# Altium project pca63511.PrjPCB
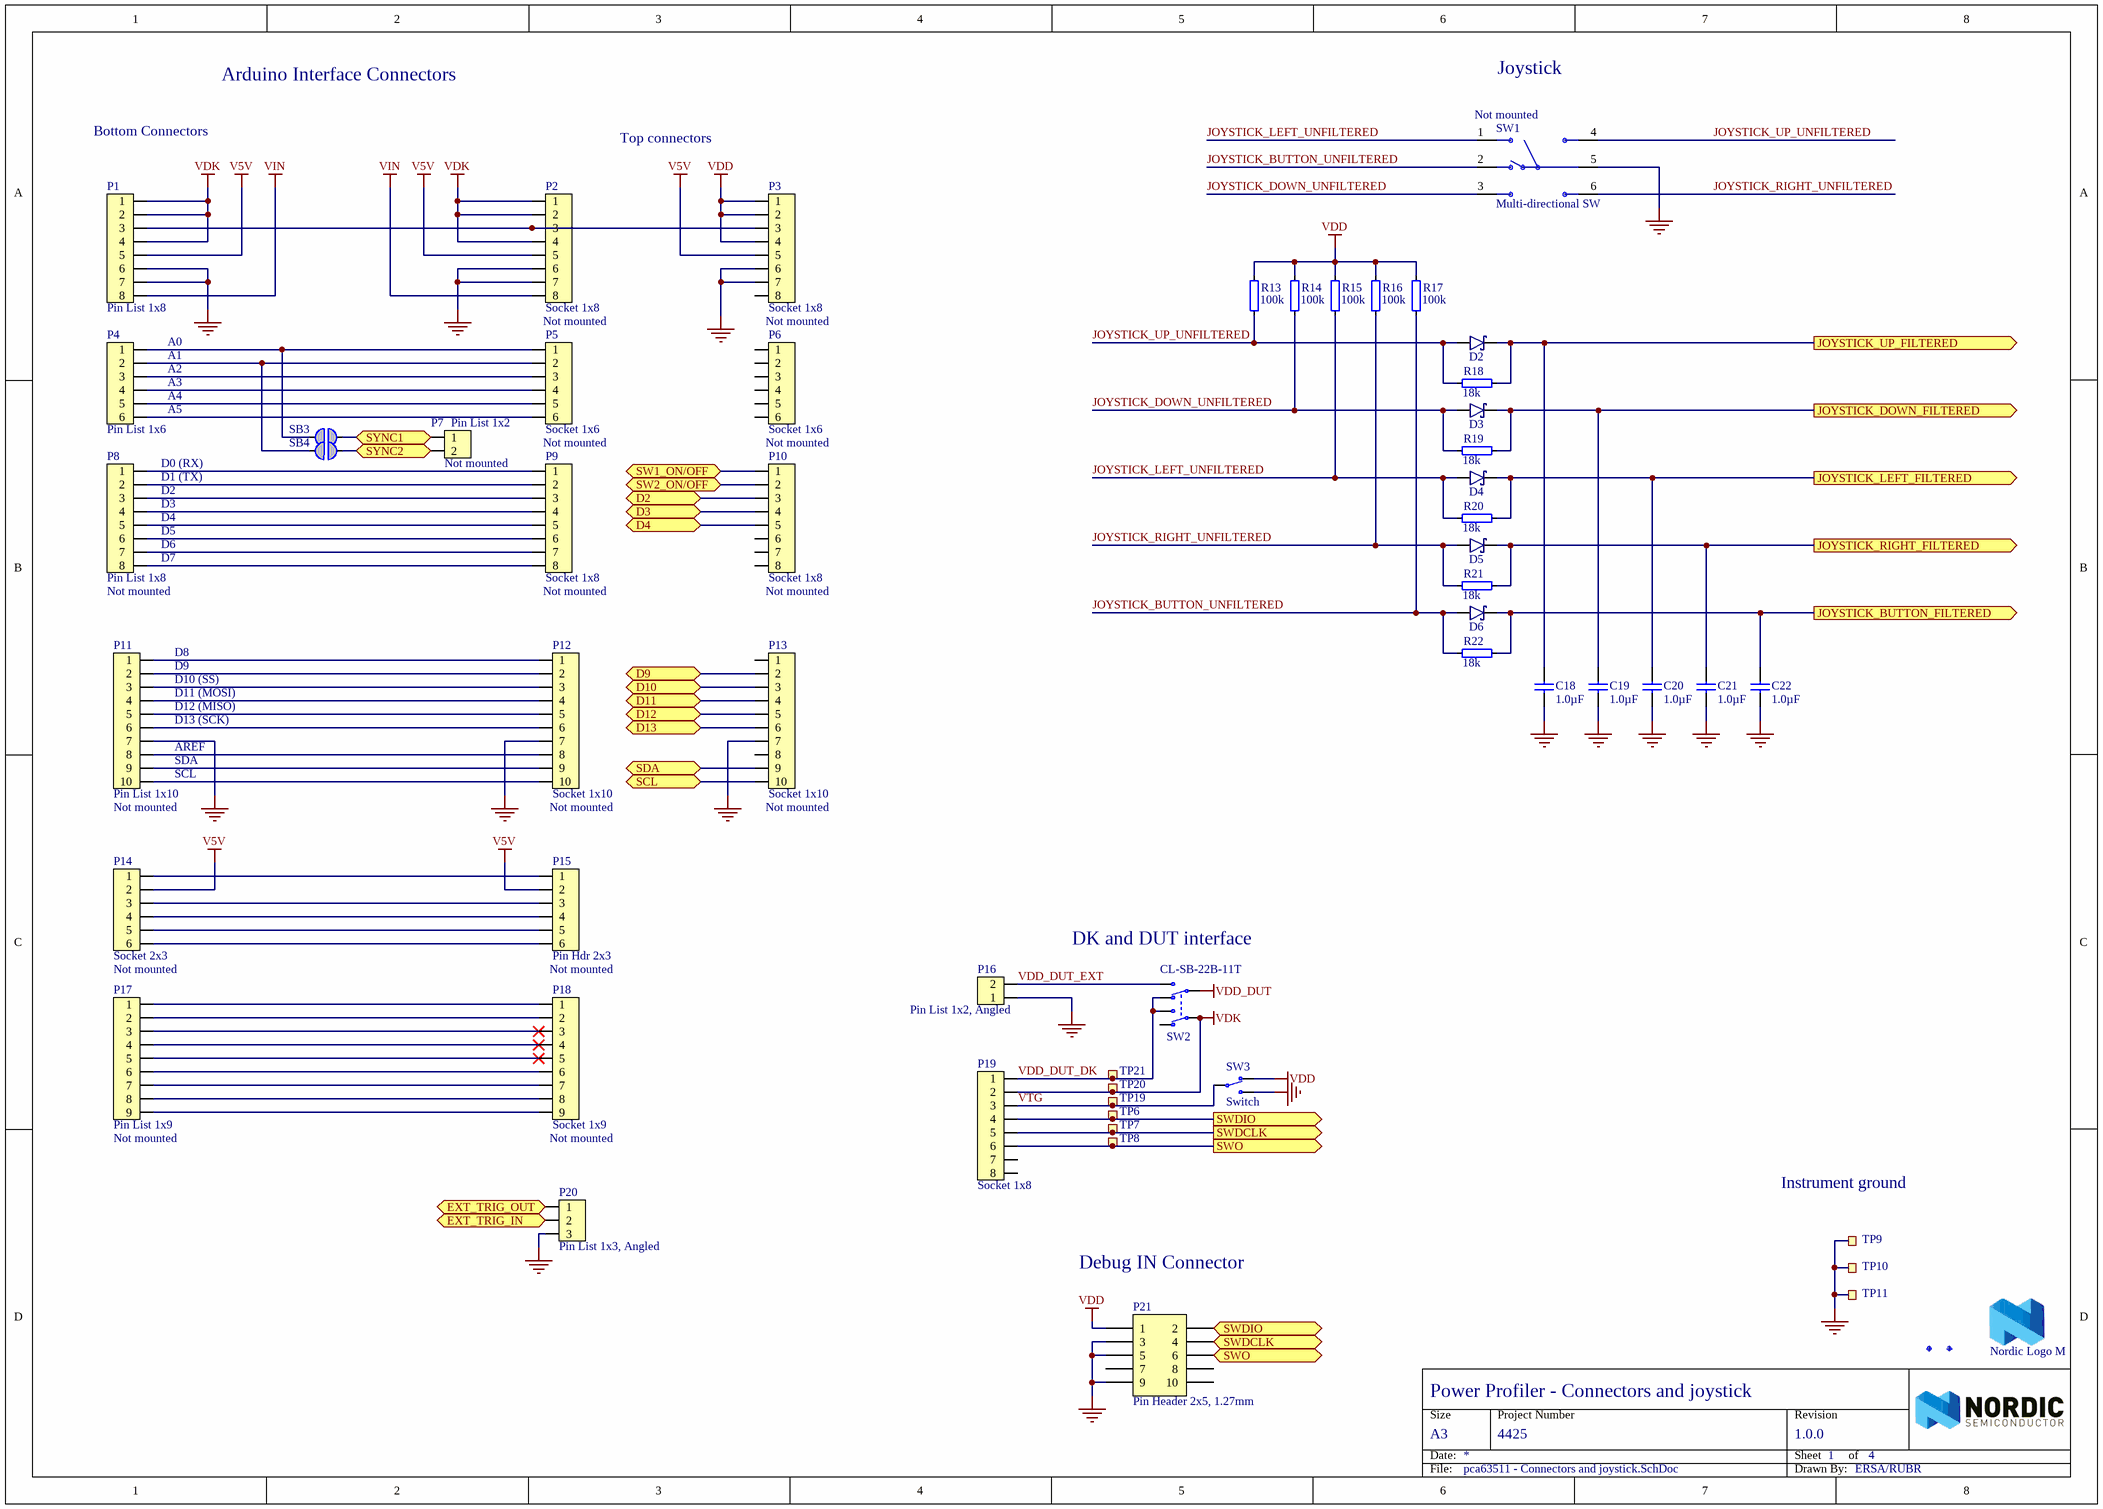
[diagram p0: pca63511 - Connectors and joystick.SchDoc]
4 sheets, 220 parts. Net scope: flat (ports and power ports of the same name join across sheets).
Board file: 400102.PcbDoc
Sheets:
  pca63511 - Connectors and joystick.SchDoc
  pca63511 - Current Measurement.SchDoc
  pca63511 - Automatic switch.SchDoc
  pca63511 - Power supply.SchDoc

## Sheet pca63511 - Connectors and joystick.SchDoc: Power Profiler - Connectors and joystick
size A3; Revision: 1.0.0; SheetNumber: 1; SheetTotal: 4; DrawnBy: ERSA/RUBR; ProjectNumber: 4425; DocumentSize: A3; PCBRevision: 0232RUBR; PCAName: PCA63511; PCBNumber: 400102

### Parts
C18  1.0µF  [CAPC1005X04L]
C19  1.0µF  [CAPC1005X04L]
C20  1.0µF  [CAPC1005X04L]
C21  1.0µF  [CAPC1005X04L]
C22  1.0µF  [CAPC1005X04L]
D2  1PS79SB30.115  [SOD-523]  (value not drawn)
D3  1PS79SB30.115  [SOD-523]  (value not drawn)
D4  1PS79SB30.115  [SOD-523]  (value not drawn)
D5  1PS79SB30.115  [SOD-523]  (value not drawn)
D6  1PS79SB30.115  [SOD-523]  (value not drawn)
Fid1  Fiducial mark  [Fiducial]  (value not drawn)
Fid2  Fiducial mark  [Fiducial]  (value not drawn)
LOGO1  Nordic Logo M  [NORDIC_LOGO_M]  (no BOM)
P1  Pin List 1x8  [LIST_1x8_SMD]
P2  Socket 1x8  Assembly: Not mounted  [SOCKET_1x8_SMD]
P3  Socket 1x8  Assembly: Not mounted  [SOCKET_1x8_SMD]
P4  Pin List 1x6  [LIST_1x6_SMD]
P5  Socket 1x6  Assembly: Not mounted  [SOCKET_1x6_SMD]
P6  Socket 1x6  Assembly: Not mounted  [SOCKET_1x6_SMD]
P7  Pin List 1x2  Assembly: Not mounted  [LIST_1x2]
P8  Pin List 1x8  Assembly: Not mounted  [LIST_1x8_SMD]
P9  Socket 1x8  Assembly: Not mounted  [SOCKET_1x8_SMD]
P10  Socket 1x8  Assembly: Not mounted  [SOCKET_1x8_SMD]
P11  Pin List 1x10  Assembly: Not mounted  [LIST_1x10_SMD]
P12  Socket 1x10  Assembly: Not mounted  [SOCKET_1x10_SMD]
P13  Socket 1x10  Assembly: Not mounted  [SOCKET_1x10_SMD]
P14  Socket 2x3  Assembly: Not mounted  [SOCKET_2x3_SMD-2.54mm-bottom]
P15  Pin Hdr 2x3  Assembly: Not mounted  [Molex 15-91-2060]
P16  Pin List 1x2, Angled  [LIST_ANG_1x2-SMD-2.54MM]
P17  Pin List 1x9  Assembly: Not mounted  [LIST_1x9_SMD]
P18  Socket 1x9  Assembly: Not mounted  [SOCKET_1x9_SMD]
P19  Socket 1x8  [SOCKET_1x8_SMD]
P20  Pin List 1x3, Angled  [LIST_ANG_1x3-SMD-2.54MM]
P21  Pin Header 2x5, 1.27mm  [HDR_2x5-SMD-1.27mm-K]
R13  100k  [RESC1005X04L]
R14  100k  [RESC1005X04L]
R15  100k  [RESC1005X04L]
R16  100k  [RESC1005X04L]
R17  100k  [RESC1005X04L]
R18  18k  [RESC1005X04L]
R19  18k  [RESC1005X04L]
R20  18k  [RESC1005X04L]
R21  18k  [RESC1005X04L]
R22  18k  [RESC1005X04L]
SB3  Solderbridge  [Solderbridge]  (value not drawn)  (no BOM)
SB4  Solderbridge  [Solderbridge]  (value not drawn)  (no BOM)
SW1  Multi-directional SW  Assembly: Not mounted  [ALPS_SKRHAAE010]
SW2  CL-SB-22B-11T  [CL-SB-22B-1x]
SW3  Switch  [CJS-120xA]
TP6  Ø1.5mm,SMD  [TP_SMD_Ø1.5mm]  (value not drawn)  (no BOM)
TP7  Ø1.5mm,SMD  [TP_SMD_Ø1.5mm]  (value not drawn)  (no BOM)
TP8  Ø1.5mm,SMD  [TP_SMD_Ø1.5mm]  (value not drawn)  (no BOM)
TP9  TP  [TEST_POINT_5001]  (value not drawn)  (no BOM)
TP10  TP  [TEST_POINT_5001]  (value not drawn)  (no BOM)
TP11  Ø1.0mm,SMD  [TP_SMD_Ø1.5MM]  (value not drawn)  (no BOM)
TP19  Ø1.5mm,SMD  [TP_SMD_Ø1.5mm]  (value not drawn)  (no BOM)
TP20  Ø1.5mm,SMD  [TP_SMD_Ø1.5mm]  (value not drawn)  (no BOM)
TP21  Ø1.5mm,SMD  [TP_SMD_Ø1.5mm]  (value not drawn)  (no BOM)

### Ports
D2 (bidir), D3 (bidir), D4 (bidir), D9 (bidir), D10 (bidir), D11 (bidir), D12 (bidir), D13 (bidir), EXT_TRIG_IN (out), EXT_TRIG_OUT (in), JOYSTICK_BUTTON_FILTERED (out), JOYSTICK_DOWN_FILTERED (out), JOYSTICK_LEFT_FILTERED (out), JOYSTICK_RIGHT_FILTERED (out), JOYSTICK_UP_FILTERED (out), SCL (bidir), SDA (bidir), SW1_ON/OFF (bidir), SW2_ON/OFF (bidir), SWDCLK (out), SWDIO (out), SWO (out), SYNC1 (bidir), SYNC2 (bidir)

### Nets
GND: C18.2 C19.2 C20.2 C21.2 C22.2 P1.6 P1.7 P2.6 P2.7 P3.6 P3.7 P11.7 P12.7 P13.7 P16.1 P20.3 P21.3 P21.5 P21.9 SW1.5 SW3.3(N.O) TP9.1 TP10.1 TP11.1
V5V: P1.5 P2.5 P3.5 P14.2 P15.2
VDD: P3.1 P3.2 P3.4 P21.1 R13.2 R14.2 R15.2 R16.2 R17.2 SW3.1(N.C)
VDD_DUT: SW2.5(COM-2)
VDK: P1.1 P1.2 P1.4 P2.1 P2.2 P2.4 P19.2 SW2.2(COM-1) TP20.1
VIN: P1.8 P2.8
D2: P10.3 ; port D2
D3: P10.4 ; port D3
D4: P10.5 ; port D4
D9: P13.2 ; port D9
D10: P13.3 ; port D10
D11: P13.4 ; port D11
D12: P13.5 ; port D12
D13: P13.6 ; port D13
EXT_TRIG_IN: P20.2 ; port EXT_TRIG_IN
EXT_TRIG_OUT: P20.1 ; port EXT_TRIG_OUT
JOYSTICK_BUTTON_FILTERED: C22.1 D6.3(C) R22.2 ; port JOYSTICK_BUTTON_FILTERED
JOYSTICK_BUTTON_UNFILTERED: D6.1(A) R17.1 R22.1 SW1.2
JOYSTICK_DOWN_FILTERED: C19.1 D3.3(C) R19.2 ; port JOYSTICK_DOWN_FILTERED
JOYSTICK_DOWN_UNFILTERED: D3.1(A) R14.1 R19.1 SW1.3
JOYSTICK_LEFT_FILTERED: C20.1 D4.3(C) R20.2 ; port JOYSTICK_LEFT_FILTERED
JOYSTICK_LEFT_UNFILTERED: D4.1(A) R15.1 R20.1 SW1.1
JOYSTICK_RIGHT_FILTERED: C21.1 D5.3(C) R21.2 ; port JOYSTICK_RIGHT_FILTERED
JOYSTICK_RIGHT_UNFILTERED: D5.1(A) R16.1 R21.1 SW1.6
JOYSTICK_UP_FILTERED: C18.1 D2.3(C) R18.2 ; port JOYSTICK_UP_FILTERED
JOYSTICK_UP_UNFILTERED: D2.1(A) R13.1 R18.1 SW1.4
SCL: P13.10 ; port SCL
SDA: P13.9 ; port SDA
SW1_ON/OFF: P10.1 ; port SW1_ON/OFF
SW2_ON/OFF: P10.2 ; port SW2_ON/OFF
SWDCLK: P19.5 P21.4 TP7.1 ; port SWDCLK
SWDIO: P19.4 P21.2 TP6.1 ; port SWDIO
SWO: P19.6 P21.6 TP8.1 ; port SWO
SYNC1: P7.1 SB3.1 ; port SYNC1
SYNC2: P7.2 SB4.1 ; port SYNC2
VDD_DUT_DK: P19.1 SW2.1(N.O-1) SW2.6(N.C-2) TP21.1
VDD_DUT_EXT: P16.2 SW2.4(N.O-2)
VTG: P19.3 SW3.2(COM) TP19.1
NetP1_3: P1.3 P2.3 P3.3
NetP4_1: P4.1 P5.1 SB3.2
NetP4_2: P4.2 P5.2 SB4.2
NetP4_3: P4.3 P5.3
NetP4_4: P4.4 P5.4
NetP4_5: P4.5 P5.5
NetP4_6: P4.6 P5.6
NetP8_1: P8.1 P9.1
NetP8_2: P8.2 P9.2
NetP8_3: P8.3 P9.3
NetP8_4: P8.4 P9.4
NetP8_5: P8.5 P9.5
NetP8_6: P8.6 P9.6
NetP8_7: P8.7 P9.7
NetP8_8: P8.8 P9.8
NetP11_1: P11.1 P12.1
NetP11_2: P11.2 P12.2
NetP11_3: P11.3 P12.3
NetP11_4: P11.4 P12.4
NetP11_5: P11.5 P12.5
NetP11_6: P11.6 P12.6
NetP11_8: P11.8 P12.8
NetP11_9: P11.9 P12.9
NetP11_10: P11.10 P12.10
NetP14_1: P14.1 P15.1
NetP14_3: P14.3 P15.3
NetP14_4: P14.4 P15.4
NetP14_5: P14.5 P15.5
NetP14_6: P14.6 P15.6
NetP17_1: P17.1 P18.1
NetP17_2: P17.2 P18.2
NetP17_3: P17.3 P18.3
NetP17_4: P17.4 P18.4
NetP17_5: P17.5 P18.5
NetP17_6: P17.6 P18.6
NetP17_7: P17.7 P18.7
NetP17_8: P17.8 P18.8
NetP17_9: P17.9 P18.9

Not connected (* = marked no-connect by the designer): P3 8; P6 1 2 3 4 5 6; P10 6 7 8; P13 1 8; P19 7 8; P21 7 8 10; SW2 3(N.C-1)

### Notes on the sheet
- Arduino Interface Connectors
- Joystick
- Bottom Connectors
- Top connectors
- A0
- (near P4) A1
- (near P4) A2
- (near P4) A3
- (near P4) A4
- (near P4) A5
- (near P8) D0 (RX)
- (near P8) D1 (TX)
- (near P8) D2
- (near P8) D3
- (near P8) D4
- (near P8) D5
- (near P8) D6
- (near P8) D7
- (near P11) D8
- (near P11) D9
- (near P11) D10 (SS)
- (near P11) D11 (MOSI)
- (near P11) D12 (MISO)
- (near P11) D13 (SCK)
- (near P11) AREF
- (near P11) SDA
- (near P11) SCL
- (near SW2) DK and DUT interface
- Instrument ground
- Debug IN Connector

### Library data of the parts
C18-C22 = C0402-1µ0: Capacitor, X5R, ±5%; Note: 6.3V; Artikkelnr Noca: 20039235; Artikkelnr Simpro: N.A.
D2-D6 = 1PS79SB30.115: Diode Schottky Vf=0.38, Vr=40V, If=200mA, Ir=500nA; Manufacturer: NXP; Artikkelnr Noca: 10029120; Artikkelnr Simpro: N.A.
Fid1 Fid2 = Fid-Mark: Artikkelnr Noca: N.A.
LOGO1 = Nordic Logo M: Nordic Logo, medium size; Artikkelnr Noca: N.A.
P1 P8 = Pin List 1x8 SMD: Pin List 1x8, 2.54mm (100mil), SMD; Manufacturer: W-CON; Manufacturer Part Number: 1125-1108S0M116R2; 2nd source part number: TSM-108-01-L-SV-P-TR; Artikkelnr Noca: 55010006; Artikkelnr Simpro: N.A.
P2 P3 P9 P10 P19 = Socket 1x8 SMD: Socket 1x8, 2.54mm (100mil), SMD; Manufacturer: W-CON; Manufacturer Part Number: 2171-108MS0CUNR1; 2nd source part number: SSM-108-F-SV-P-TR; Artikkelnr Noca: 55030002; Artikkelnr Simpro: N.A.
P4 = Pin List 1x6 SMD: Pin List 1x6, 2.54mm (100mil), SMD; Manufacturer: W-CON; Manufacturer Part Number: 1125-1106S0M116R2; 2nd source part number: TSM-106-01-L-SV-P-TR; Artikkelnr Noca: 55019252; Artikkelnr Simpro: N.A.
P5 P6 = Socket 1x6 SMD: Socket 1x6, 2.54mm (100mil), SMD; Manufacturer: W-CON; Manufacturer Part Number: 2171-106MS0CUNR1; 2nd source part number: SSM-106-F-SV-P-TR; Artikkelnr Noca: 55030001; Artikkelnr Simpro: N.A.
P7 = Pin List 1x2: Pin List 1x2, 2.54mm (100mil); Artikkelnr Noca: 56019040; Artikkelnr Simpro: N.A.
P11 = Pin List 1x10 SMD: Pin List 1x10, 2.54mm (100mil), SMD; Manufacturer: W-CON; Manufacturer Part Number: 1125-1110S0M116R2; 2nd source part number: TSM-110-01-L-SV-P-TR; Artikkelnr Noca: 55019254; Artikkelnr Simpro: N.A.
P12 P13 = Socket 1x10 SMD: Socket 1x10, 2.54mm (100mil), SMD; Manufacturer: W-CON; Manufacturer Part Number: 2171-110MS0CUNR1; 2nd source part number: SSM-110-F-SV-P-TR; Artikkelnr Noca: 55030004; Artikkelnr Simpro: N.A.
P14 = Socket 2x3 SMD Bottom: Socket 2x3, 2.54mm (100mil), SMD; Manufacturer: W-CON; Manufacturer Part Number: 2171-203MS0CUNR1; 2nd source part number: SSM-103-F-DV-P-TR; Artikkelnr Noca: 55019255; Artikkelnr Simpro: N.A.
P15 = Pin Header 2x3 SMD: Pin Header 2x3, 2.54mm (100mil) SMD; Manufacturer: W-CON; Manufacturer Part Number: 1125-1203S0M116R1; 2nd source part number: TSM-103-01-L-DV; Artikkelnr Noca: 55010007; Artikkelnr Simpro: N.A.
P16 = Pin List Ang 1x2 SMD, 2.54mm: Pin List 1x2, 2.54mm (100mil), Right Angled, SMD; Manufacturer: W-CON; Manufacturer Part Number: 1125B-1102S0Z135R2; 2nd source part number: TSM-102-01-L-SH-A; Artikkelnr Noca: 55010023; Artikkelnr Simpro: N.A.
P17 = Pin List 1x9 SMD: Pin List 1x9, 2.54mm (100mil), SMD; Manufacturer: W-CON; Manufacturer Part Number: 1125-1109S0M116R2; 2nd source part number: TSM-109-01-L-SV-P-TR; Artikkelnr Noca: 55010024; Artikkelnr Simpro: N.A.
P18 = Socket 1x9 SMD: Socket 1x9, 2.54mm (100mil), SMD; Manufacturer: W-CON; Manufacturer Part Number: 2171-109MS0CUNR1; 2nd source part number: SSM-109-L-SV; Artikkelnr Noca: 55030003; Artikkelnr Simpro: N.A.
P20 = Pin List Ang 1x3 SMD, 2.54mm: Pin List 1x3, 2.54mm (100mil), Right Angled, SMD; Manufacturer: W-CON; Manufacturer Part Number: 1125B-1103S0Z135R2; 2nd source part number: TSM-103-01-L-SH-A; Artikkelnr Noca: 55019288; Artikkelnr Simpro: N.A.
P21 = Pin Header 2x5 SMD, 1.27mm, KS: Pin Header 2x5, 1.27mm (50mil), SMD, Keying Shroud; Manufacturer: W-CON; Manufacturer Part Number: 3132-10MS0BK00R1; 2nd source part number: FTSH-105-01-F-DV-K; Artikkelnr Noca: 55010009; Artikkelnr Simpro: N.A.
R13-R17 = R0402-100k: Resistor, ±1%, 0.063W; Note: Chip Res 1%; Artikkelnr Noca: 27049121; Artikkelnr Simpro: N.A.; Value Ohm: 100000
R18-R22 = R0402-18k: Resistor, ±1%, 0.063W; Note: Chip Res 1%; Artikkelnr Noca: 27049103; Artikkelnr Simpro: N.A.; Value Ohm: 18000
SB3 SB4 = Solderbridge: Artikkelnr Noca: N.A.
SW1 = ALPS_SKRHAAE010: ALPS - SKRHAAE010, Multi-directional Switches 4-directn cntr push w/o boss 200K cycles, SMD, 7.5x7.5x5mm; Artikkelnr Noca: 50019040; Artikkelnr Simpro: N.A.
SW2 = CL-SB-22B-11T: Slide Switch DPDT 200mA 12V; Manufacturer: Copal Electronics Inc; Artikkelnr Noca: 50019109; Artikkelnr Simpro: N.A.
SW3 = CJS-1200TA: SMD slide Switch (ON-ON); Manufacturer: Copal Electronics Inc; Artikkelnr Noca: 50019068; Artikkelnr Simpro: N.A.
TP6-TP8 TP19-TP21 = TP_SMD_Ø1.5MM: 1.0mm circular SMD testpad; Manufacturer: Nordic Semiconductor; Artikkelnr Noca: N.A.
TP9 TP10 = TP - Keystone 5001: Miniature THM Test Point -Black P/N 5001; Manufacturer Part Number: 5001; 2nd source part number: 5001K-ND; Note: Keystone 5001, BLACK; Artikkelnr Noca: N.A.; Assembly: Not mounted
TP11 = TP_SMD_Ø1.0MM: 1.0mm circular SMD testpad; Manufacturer: Nordic Semiconductor; Artikkelnr Noca: N.A.

## Sheet pca63511 - Current Measurement.SchDoc: Power Profiler - Current Measurement
size A3; Revision: 1.0.0; SheetNumber: 2; SheetTotal: 4; DrawnBy: ERSA/RUBR; ProjectNumber: 4425; DocumentSize: A3; PCBRevision: 0232RUBR; PCAName: PCA63511; PCBNumber: 400102
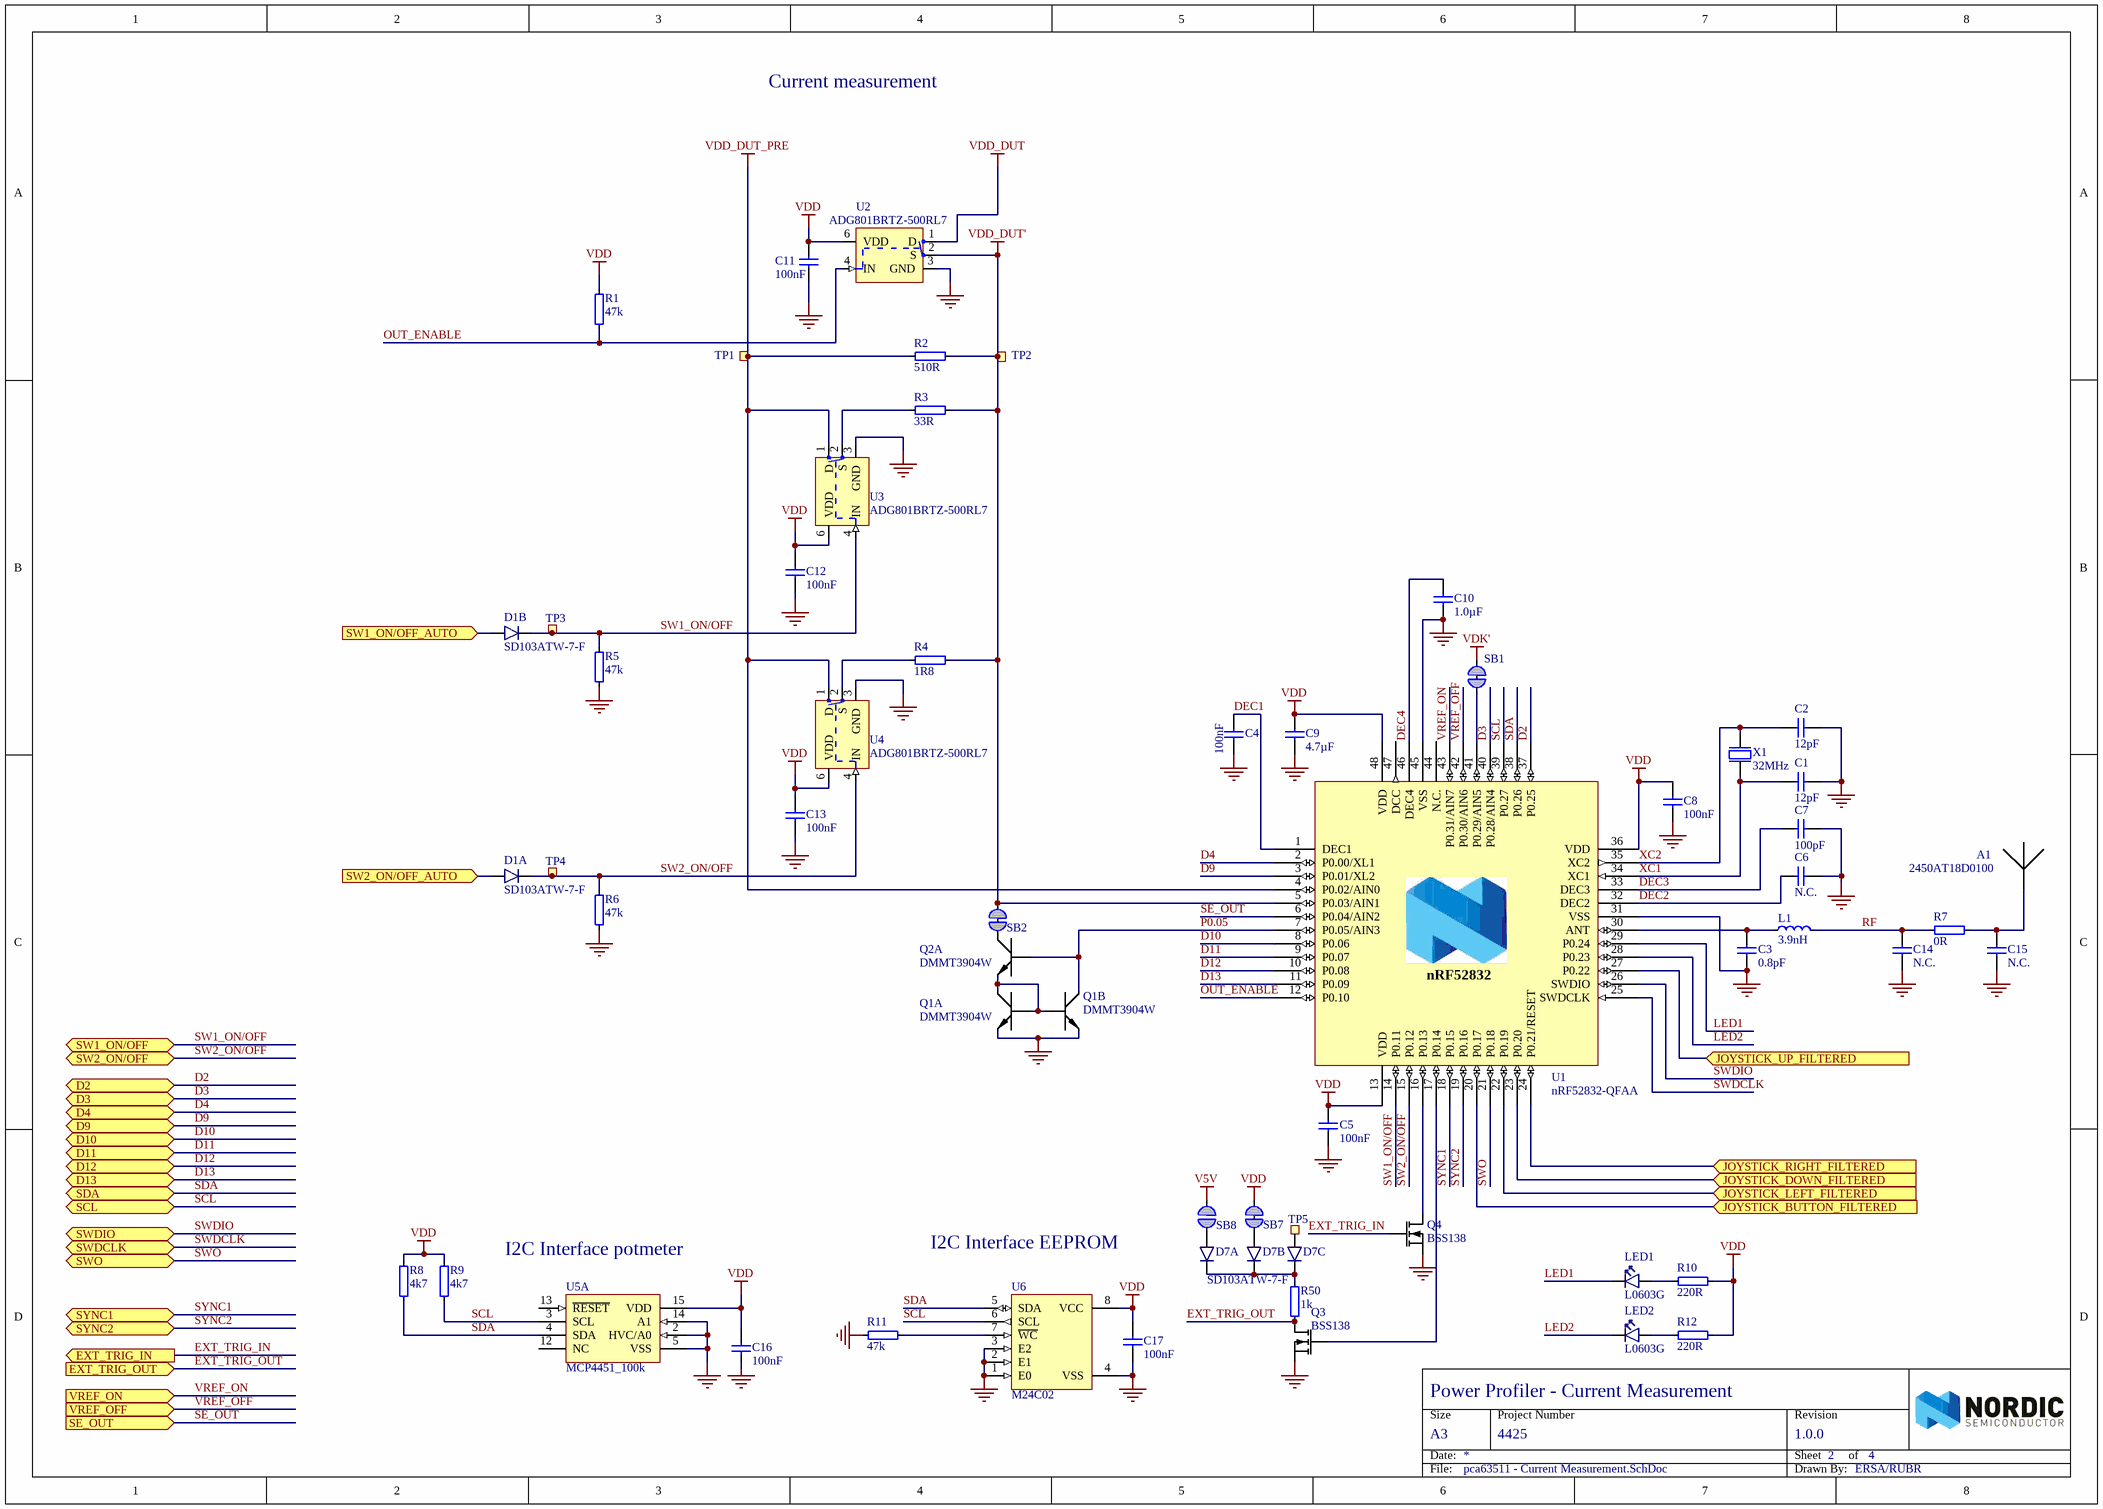
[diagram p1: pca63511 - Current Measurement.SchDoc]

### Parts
A1  2450AT18D0100  [2450AT18D0100_STD]
C1  12pF  [CAPC1005X04L]
C2  12pF  [CAPC1005X04L]
C3  0.8pF  [CAPC1005X04L]
C4  100nF  [CAPC1005X04L]
C5  100nF  [CAPC1005X04L]
C6  N.C.  [CAPC1005X04L]
C7  100pF  [CAPC1005X04L]
C8  100nF  [CAPC1005X04L]
C9  4.7µF  [CAPC1608X06L]
C10  1.0µF  [CAPC1608X06L]
C11  100nF  [CAPC1005X04L]
C12  100nF  [CAPC1005X04L]
C13  100nF  [CAPC1005X04L]
C14  N.C.  [CAPC1005X04L]
C15  N.C.  [CAPC1005X04L]
C16  100nF  [CAPC1005X04L]
C17  100nF  [CAPC1005X04L]
D1  SD103ATW-7-F  [SOT-363]  (parts A,B of 3)
D7  SD103ATW-7-F  [SOT-363]  (parts A,B,C of 3)
L1  3.9nH  [INDC1005X04L]
LED1  L0603G  [LED_0603_G]
LED2  L0603G  [LED_0603_G]
Q1  DMMT3904W  [SOT-363]  (parts A,B of 2)
Q2  DMMT3904W  [SOT-363]  (part A of 2)
Q3  BSS138  [SOT65P210X110-3N]
Q4  BSS138  [SOT65P210X110-3N]
R1  47k  [RESC1005X04L]
R2  510R  [RESC1005X04L]
R3  33R  [RESC1005X04L]
R4  1R8  [RESC1005X04L]
R5  47k  [RESC1005X04L]
R6  47k  [RESC1005X04L]
R7  0R  [RESC1005X04L]
R8  4k7  [RESC1005X04L]
R9  4k7  [RESC1005X04L]
R10  220R  [RESC1005X04L]
R11  47k  [RESC1005X04L]
R12  220R  [RESC1005X04L]
R50  1k  [RESC1005X04L]
SB1  Solderbridge  [Solderbridge_Shorted]  (value not drawn)  (net tie, no BOM)
SB2  Solderbridge  [Solderbridge_Shorted]  (value not drawn)  (net tie, no BOM)
SB7  Solderbridge  [Solderbridge_Shorted]  (value not drawn)  (net tie, no BOM)
SB8  Solderbridge  [Solderbridge]  (value not drawn)  (no BOM)
TP1  Ø1.5mm,SMD  [TP_SMD_Ø1.5mm]  (value not drawn)  (no BOM)
TP2  Ø1.5mm,SMD  [TP_SMD_Ø1.5mm]  (value not drawn)  (no BOM)
TP3  Ø1.5mm,SMD  [TP_SMD_Ø1.5mm]  (value not drawn)  (no BOM)
TP4  Ø1.5mm,SMD  [TP_SMD_Ø1.5mm]  (value not drawn)  (no BOM)
TP5  TP  [TEST_POINT_5000]  (value not drawn)  (no BOM)
U1  nRF52832-QFAA  [QFN40P600X600X90-48N]
U2  ADG801BRTZ-500RL7  [SOT95P280X145-6N]
U3  ADG801BRTZ-500RL7  [SOT95P280X145-6N]
U4  ADG801BRTZ-500RL7  [SOT95P280X145-6N]
U5  MCP4451_100k  [QFN50P400X400X80_HS-21N]  (part A of 5)
U6  M24C02  [TSOP65P640X120-8N]
X1  32MHz  [BT-XTAL_2016]

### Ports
D2 (bidir), D3 (bidir), D4 (bidir), D9 (bidir), D10 (bidir), D11 (bidir), D12 (bidir), D13 (bidir), EXT_TRIG_IN (out), EXT_TRIG_OUT (in), JOYSTICK_BUTTON_FILTERED (in), JOYSTICK_DOWN_FILTERED (in), JOYSTICK_LEFT_FILTERED (in), JOYSTICK_RIGHT_FILTERED (in), JOYSTICK_UP_FILTERED (in), SCL (bidir), SDA (bidir), SE_OUT (in), SW1_ON/OFF (bidir), SW1_ON/OFF_AUTO (in), SW2_ON/OFF (bidir), SW2_ON/OFF_AUTO (in), SWDCLK (bidir), SWDIO (bidir), SWO (bidir), SYNC1 (bidir), SYNC2 (bidir), VREF_OFF (in), VREF_ON (in)

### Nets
GND: A1.2(GND) C1.2 C2.2 C3.1 C4.2 C5.2 C6.1 C7.2 C8.2 C9.2 C10.1 C11.2 C12.2 C13.2 C14.1 C15.1 C16.1 C17.2 Q1.4(E1) Q1.5(E2) Q3.2(S) Q4.2(S) R5.1 R6.2 R11.1 U1.31(VSS) U1.45(VSS) U1.49(GND) U2.3(GND) U3.3(GND) U4.3(GND) U5.2(HVC/A0) U5.5(VSS) U5.14(A1) U5.21(VSS) U6.1(E0) U6.2(E1) U6.3(E2) U6.4(VSS) X1.2(GND) X1.4(GND)
V5V: SB8.1
VDD: C5.1 C8.1 C9.1 C11.1 C12.1 C13.1 C16.2 C17.1 R1.2 R8.2 R9.2 R10.2 R12.2 SB7.1 U1.13(VDD) U1.36(VDD) U1.48(VDD) U2.6(VDD) U3.6(VDD) U4.6(VDD) U5.15(VDD) U6.8(VCC)
VDD_DUT: U2.1(D)
VDD_DUT': R2.2 R3.2 R4.2 SB2.1 TP2.1 U1.5(P0.03/AIN1) U2.2(S)
VDD_DUT_PRE: R2.1 TP1.1 U1.4(P0.02/AIN0) U3.1(D) U4.1(D)
VDK': SB1.1
D2: U1.37(P0.25) ; port D2
D3: U1.40(P0.28/AIN4) ; port D3
D4: U1.2(P0.00/XL1) ; port D4
D9: U1.3(P0.01/XL2) ; port D9
D10: U1.8(P0.06) ; port D10
D11: U1.9(P0.07) ; port D11
D12: U1.10(P0.08) ; port D12
D13: U1.11(P0.09) ; port D13
DEC1: C4.1 U1.1(DEC1)
DEC2: C6.2 U1.32(DEC2)
DEC3: C7.1 U1.33(DEC3)
DEC4: C10.2 U1.46(DEC4)
EXT_TRIG_IN: Q4.1(G) ; port EXT_TRIG_IN
EXT_TRIG_OUT: Q3.3(D) R50.1 ; port EXT_TRIG_OUT
JOYSTICK_BUTTON_FILTERED: U1.20(P0.17) ; port JOYSTICK_BUTTON_FILTERED
JOYSTICK_DOWN_FILTERED: U1.23(P0.20) ; port JOYSTICK_DOWN_FILTERED
JOYSTICK_LEFT_FILTERED: U1.22(P0.19) ; port JOYSTICK_LEFT_FILTERED
JOYSTICK_RIGHT_FILTERED: U1.24(P0.21/RESET) ; port JOYSTICK_RIGHT_FILTERED
JOYSTICK_UP_FILTERED: U1.27(P0.22) ; port JOYSTICK_UP_FILTERED
LED1: LED1.1(C) U1.29(P0.24)
LED2: LED2.1(C) U1.28(P0.23)
OUT_ENABLE: R1.1 U1.12(P0.10) U2.4(IN)
P0.05: Q1.6(C2) Q2.2(B1) U1.7(P0.05/AIN3)
RF: C14.2 L1.2 R7.1
SCL: R9.1 U1.39(P0.27) U5.3(SCL) U6.6(SCL) ; port SCL
SDA: R8.1 U1.38(P0.26) U5.4(SDA) U6.5(SDA) ; port SDA
SE_OUT: U1.6(P0.04/AIN2) ; port SE_OUT
SW1_ON/OFF: D1.2(C2) R5.2 TP3.1 U1.14(P0.11) U3.4(IN) ; port SW1_ON/OFF
SW1_ON/OFF_AUTO: D1.5(A2) ; port SW1_ON/OFF_AUTO
SW2_ON/OFF: D1.1(C1) R6.1 TP4.1 U1.15(P0.12) U4.4(IN) ; port SW2_ON/OFF
SW2_ON/OFF_AUTO: D1.6(A1) ; port SW2_ON/OFF_AUTO
SWDCLK: U1.25(SWDCLK) ; port SWDCLK
SWDIO: U1.26(SWDIO) ; port SWDIO
SWO: U1.21(P0.18) ; port SWO
SYNC1: U1.18(P0.15) ; port SYNC1
SYNC2: U1.19(P0.16) ; port SYNC2
VREF_OFF: U1.42(P0.30/AIN6) ; port VREF_OFF
VREF_ON: U1.43(P0.31/AIN7) ; port VREF_ON
XC1: C1.1 U1.34(XC1) X1.1(inp)
XC2: C2.1 U1.35(XC2) X1.3(out)
NetA1_1: A1.1 C15.2 R7.2
NetC3_2: C3.2 L1.1 U1.30(ANT)
NetD7_1: D7.1(C1) D7.2(C2) D7.3(C3) R50.2
NetD7_4: D7.4(A3) TP5.1
NetD7_5: D7.5(A2) SB7.2
NetD7_6: D7.6(A1) SB8.2
NetLED1_2: LED1.2(A) R10.1
NetLED2_2: LED2.2(A) R12.1
NetQ1_1: Q1.1(B2) Q1.2(B1) Q1.3(C1) Q2.4(E1)
NetQ2_3: Q2.3(C1) SB2.2
NetQ3_1: Q3.1(G) U1.17(P0.14)
NetQ4_3: Q4.3(D) U1.16(P0.13)
NetR3_1: R3.1 U3.2(S)
NetR4_1: R4.1 U4.2(S)
NetR11_2: R11.2 U6.7(~{WC})
NetSB1_2: SB1.2 U1.41(P0.29/AIN5)

Not connected (* = marked no-connect by the designer): U1 44(N.C.) 47(DCC); U5 12(NC) 13(~{RESET})

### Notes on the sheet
- Current measurement
- I2C Interface potmeter
- I2C Interface EEPROM

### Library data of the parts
A1 = Johanson 2450AT18D0100_STD: 2.45 GHz chip antenna; Manufacturer: Johanson Technology; 2nd source part number: 609-2450AT18D0100E; Artikkelnr Noca: 53059035; Artikkelnr Simpro: N.A.
C1 C2 = C0402-12p: Capacitor, NP0, ±2%; Note: 50V; Artikkelnr Noca: 20029159; Artikkelnr Simpro: N.A.
C3 = C0402-0.8p: Capacitor, NP0, ±5%; Note: 50V; Artikkelnr Noca: 20029147; Artikkelnr Simpro: N.A.
C4 C5 C8 C11-C13 C16 C17 = C0402-100n: Capacitor, X7R, ±10%; Note: 16V; Artikkelnr Noca: 20039200; Artikkelnr Simpro: N.A.
C6 = C0402-N.C.: Not mounted; Note: Chip Cap; Artikkelnr Noca: N.A.; Assembly: Not mounted
C7 = C0402-100p: Capacitor, NP0, ±5%; Note: 50V; Artikkelnr Noca: 20029135; Artikkelnr Simpro: N.A.
C9 = C0603-4µ7: Capacitor, X5R, ±10%; Note: 6.3V; Artikkelnr Noca: 20069060; Artikkelnr Simpro: N.A.
C10 = C0603-1µ0: Capacitor, X7R, ±10%; Note: 16V; Artikkelnr Noca: 20039335; Artikkelnr Simpro: N.A.
C14 C15 = C0402-N.C.: Not mounted; Note: Chip Cap; Artikkelnr Noca: N.A.
D1 D7 = SD103ATW-7-F: Surface Mount Schottky Barrier Diode Array; Manufacturer: Diodes Incorporated; 2nd source part number: 177-3507; Artikkelnr Noca: 10029109; Artikkelnr Simpro: N.A.
L1 = L0402-3n9: Inductor, 170mA, ±0.1nH; Manufacturer: Murata; Manufacturer Part Number: LQP15MN3N9B02D; Note: High frequency chip inductor ±5%; Artikkelnr Noca: 33029151; Artikkelnr Simpro: N.A.
LED1 LED2 = EL19-21SYGC: LED 0603, EL19-21SYGC; Manufacturer: Everlight; Manufacturer Part Number: 19-21SYGC/S530-E1/TR8; Note: 16 mcd @ 20 mA; Artikkelnr Noca: 13019044; Artikkelnr Simpro: N.A.
Q1 Q2 = DMMT3904W-7-F: 40V Matched pair NPN Small signal transistor; Manufacturer: Diodes Incorporated; 2nd source part number: 206-1407; Artikkelnr Noca: 35010017; Artikkelnr Simpro: N.A.
Q3 Q4 = BSS138PW: 60 V, 320 mA N-channel Trench MOSFET; Manufacturer: NXP; Manufacturer Part Number: BSS138PW,115; 2nd source part number: 568-10309-1-ND; Artikkelnr Noca: 35019197; Artikkelnr Simpro: N.A.
R1 R5 R6 R11 = R0402-47k: Resistor, ±1%, 0.063W; Note: Chip Res 1%; Artikkelnr Noca: 27049113; Artikkelnr Simpro: N.A.; Value Ohm: 47000
R2 = R0402-510_0.1%: Resistor, ±0.1%, 0.063W; Note: Chip Res 0.1%; Artikkelnr Noca: 27460057; Artikkelnr Simpro: N.A.; Value Ohm: 510
R3 = R0402-33R_0.1%: Resistor, ±0.1%, 0.063W; Note: Chip Res 0.1%; Artikkelnr Noca: 27460063; Artikkelnr Simpro: N.A.; Value Ohm: 33
R4 = R0402-1R8: Resistor, ±1%, 0.063W; Artikkelnr Noca: 27049007; Artikkelnr Simpro: N.A.; Note: Chip Res 1%; Value Ohm: 1.8
R7 = R0402-0R: Resistor, ±5%, 0.063W; Note: Chip Res 5%; Artikkelnr Noca: 27049000; Artikkelnr Simpro: N.A.; Value Ohm: 0
R8 R9 = R0402-4k7: Resistor, ±1%, 0.063W; Note: Chip Res 1%; Artikkelnr Simpro: N.A.; Value Ohm: 4700; Artikkelnr Noca: 27049089
R10 R12 = R0402-220: Resistor, ±1%, 0.063W; Note: Chip Res 1%; Artikkelnr Noca: 27049057; Artikkelnr Simpro: N.A.; Value Ohm: 220
R50 = R0402-1k0: Resistor, ±1%, 0.063W; Note: Chip Res 1%; Artikkelnr Noca: 27049073; Artikkelnr Simpro: N.A.; Value Ohm: 1000
SB1 SB2 SB7 = Solderbridge Shorted: Shorted Solderbridge; Artikkelnr Noca: N.A.
SB8 = Solderbridge: Artikkelnr Noca: N.A.
TP1-TP4 = TP_SMD_Ø1.5MM: as TP6 on sheet pca63511 - Connectors and joystick
TP5 = TP - Keystone 5000: Miniature THM Test Point -Red P/N 5000; Manufacturer Part Number: 5000; 2nd source part number: 5000K-ND; Note: Keystone 5000, RED; Artikkelnr Noca: N.A.; Assembly: Not Mounted
U1 = nRF52832-QFAA: Multi-protocol Bluetooth Low Energy and 2.4GHz proprietary system-on-chip; Manufacturer: Nordic Semiconductor; Artikkelnr Noca: 15079306; Artikkelnr Simpro: N.A.
U2-U4 = ADG801BRTZ-500RL7: SWITCH SPST SOT23-6; Manufacturer: Analog Devices; 2nd source part number: 237-6778; Note: -40°C ~ 125°C; Artikkelnr Noca: 15079991; Artikkelnr Simpro: N.A.
U5 = MCP4451_100k: Quad Digital Potentiometer, 100k, 257 taps, I2C interface, Volatile Memory, 1.8-5.5V; Manufacturer: Microchip Technology; Manufacturer Part Number: MCP4451-104E/ML; 2nd source part number: 579-MCP4451-104E/ML; Artikkelnr Noca: 15070064; Artikkelnr Simpro: N.A.
U6 = M24C02-FDW6TP: 2-Kbit serial I²C bus EEPROM; Manufacturer: STMicroelectronics; Artikkelnr Noca: 15020011; Artikkelnr Simpro: N.A.
X1 = XTAL_SMD2016_32MHz_8pF_Kyocera: XTAL SMD 2016, 32MHz, Cl=8pF, Tot: ±40ppm; Manufacturer Part Number: CX2016DB32000D0WZRC1; Note: XTAL SMD 32.000MHz; Artikkelnr Noca: 22010022; Artikkelnr Simpro: N.A.

## Sheet pca63511 - Automatic switch.SchDoc: Power Profiler - Automatic switch
size A3; Revision: 1.0.0; SheetNumber: 3; SheetTotal: 4; DrawnBy: ERSA/RUBR; ProjectNumber: 4425; DocumentSize: A3; PCBRevision: 0232RUBR; PCAName: PCA63511; PCBNumber: 400102
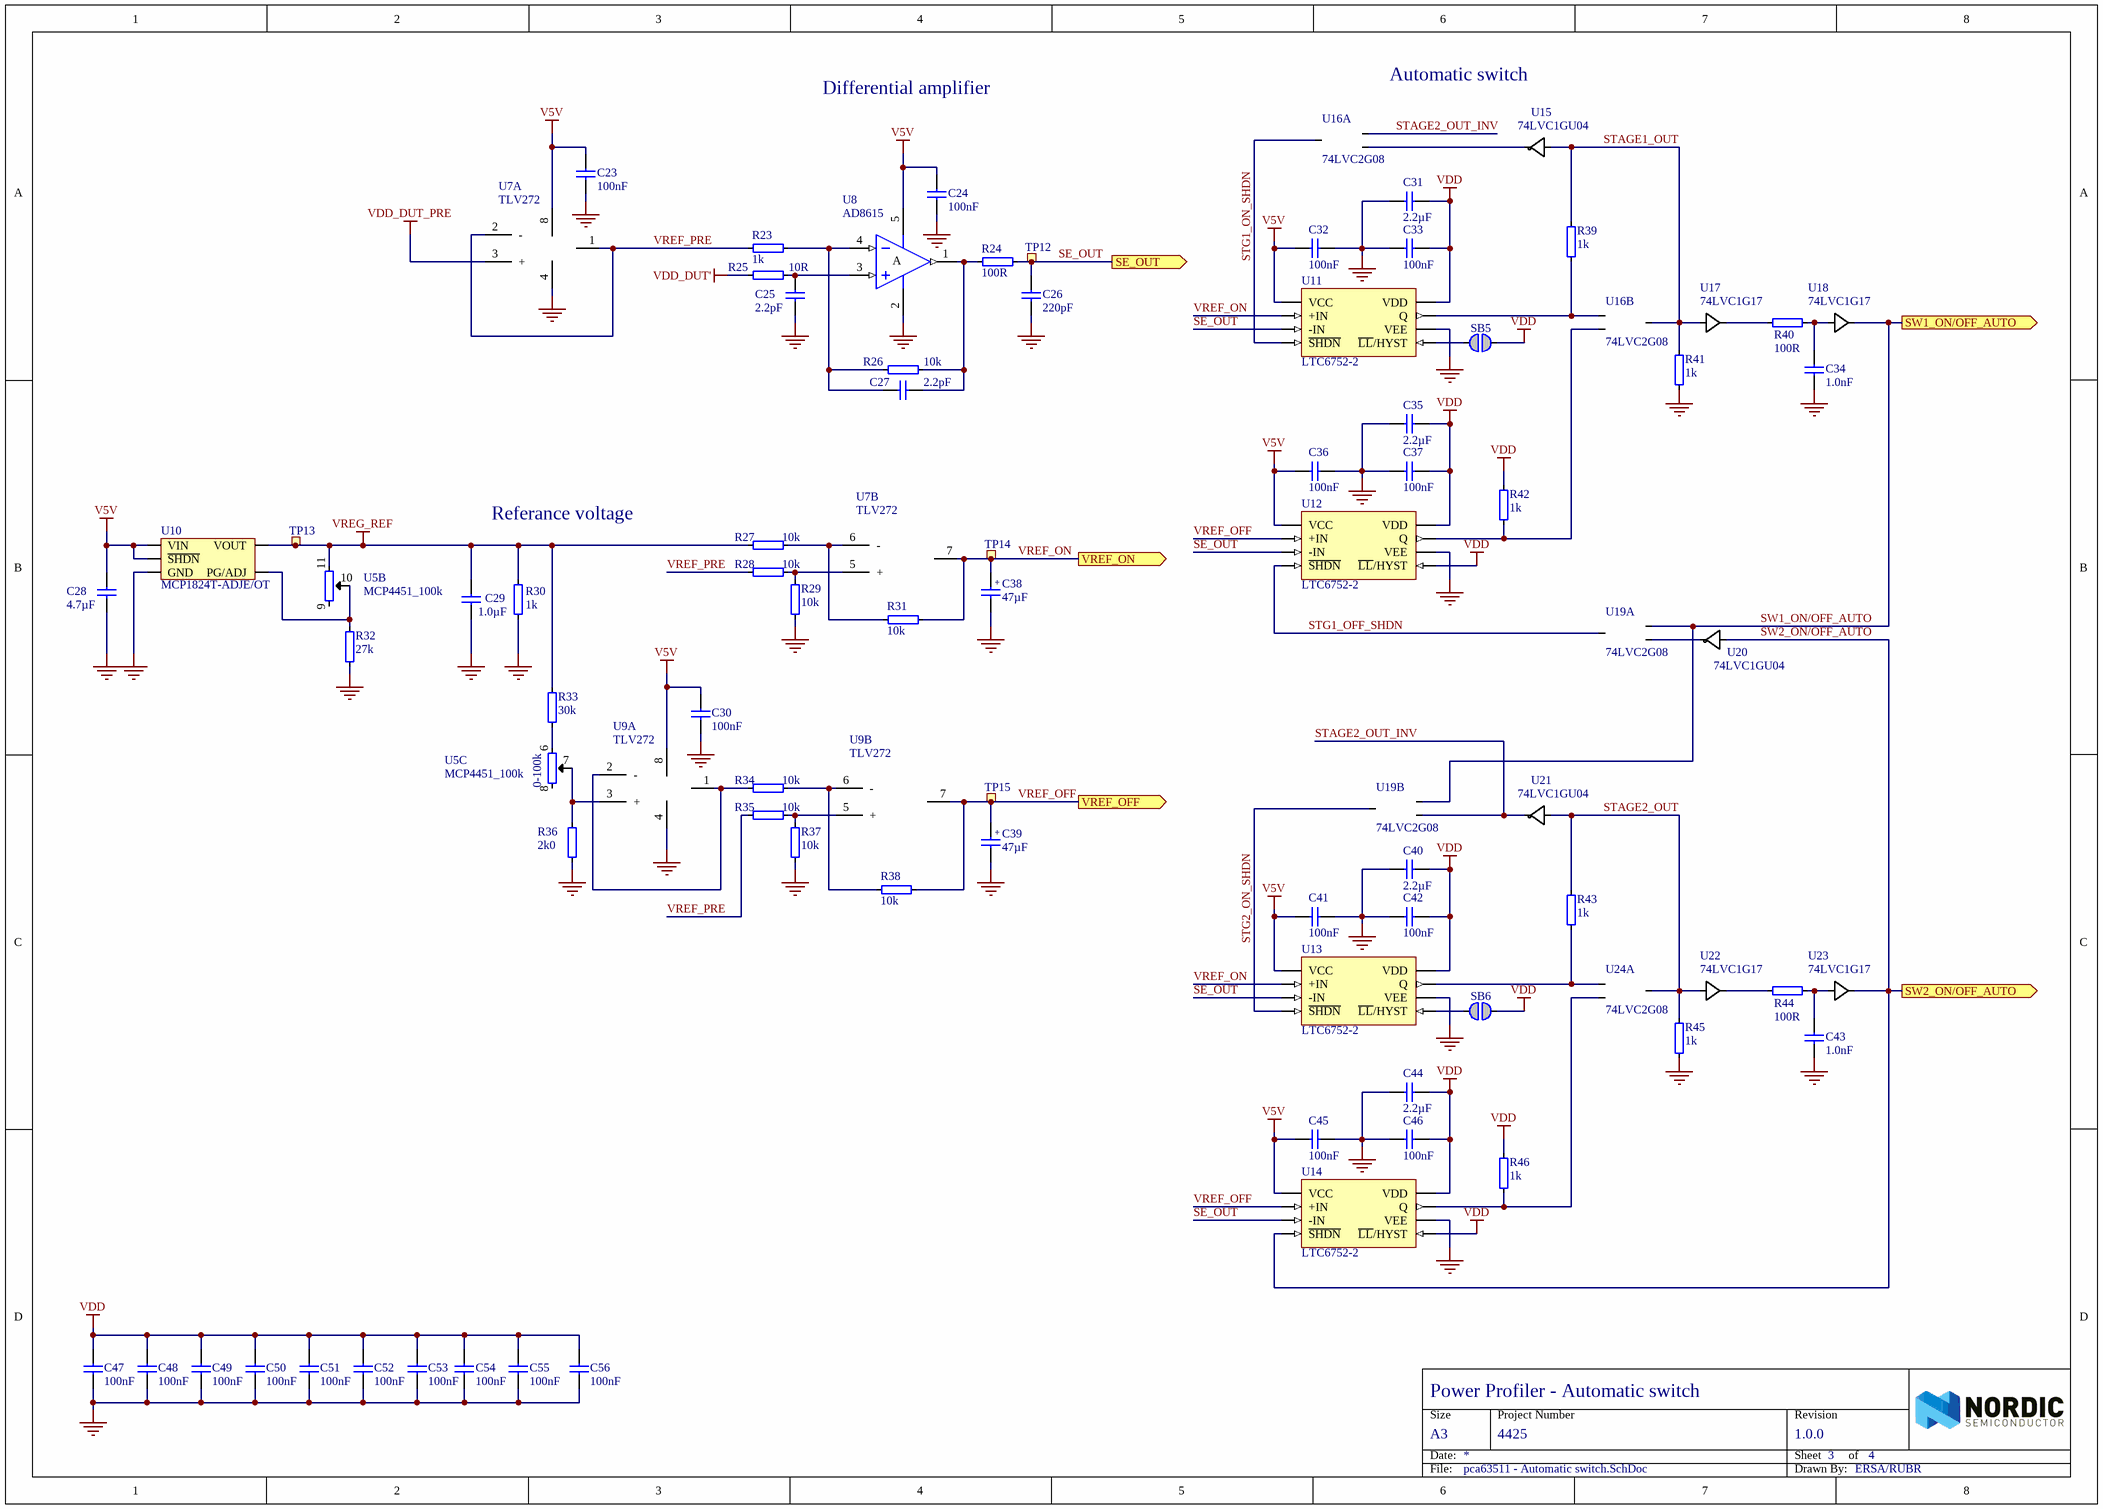
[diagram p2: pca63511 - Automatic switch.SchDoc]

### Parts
C23  100nF  [CAPC1005X04L]
C24  100nF  [CAPC1005X04L]
C25  2.2pF  [CAPC1005X04L]
C26  220pF  [CAPC1005X04L]
C27  2.2pF  [CAPC1005X04L]
C28  4.7µF  [CAPC1005X04L]
C29  1.0µF  [CAPC1005X04L]
C30  100nF  [CAPC1005X04L]
C31  2.2µF  [CAPC1005X04L]
C32  100nF  [CAPC1005X04L]
C33  100nF  [CAPC1005X04L]
C34  1.0nF  [CAPC1005X04L]
C35  2.2µF  [CAPC1005X04L]
C36  100nF  [CAPC1005X04L]
C37  100nF  [CAPC1005X04L]
C38  47µF  [CAPMP3216X18N]
C39  47µF  [CAPMP3216X18N]
C40  2.2µF  [CAPC1005X04L]
C41  100nF  [CAPC1005X04L]
C42  100nF  [CAPC1005X04L]
C43  1.0nF  [CAPC1005X04L]
C44  2.2µF  [CAPC1005X04L]
C45  100nF  [CAPC1005X04L]
C46  100nF  [CAPC1005X04L]
C47  100nF  [CAPC1005X04L]
C48  100nF  [CAPC1005X04L]
C49  100nF  [CAPC1005X04L]
C50  100nF  [CAPC1005X04L]
C51  100nF  [CAPC1005X04L]
C52  100nF  [CAPC1005X04L]
C53  100nF  [CAPC1005X04L]
C54  100nF  [CAPC1005X04L]
C55  100nF  [CAPC1005X04L]
C56  100nF  [CAPC1005X04L]
R23  1k  [RESC1005X04L]
R24  100R  [RESC1005X04L]
R25  10R  [RESC1005X04L]
R26  10k  [RESC1005X04L]
R27  10k  [RESC1005X04L]
R28  10k  [RESC1005X04L]
R29  10k  [RESC1005X04L]
R30  1k  [RESC1005X04L]
R31  10k  [RESC1005X04L]
R32  27k  [RESC1005X04L]
R33  30k  [RESC1005X04L]
R34  10k  [RESC1005X04L]
R35  10k  [RESC1005X04L]
R36  2k0  [RESC1005X04L]
R37  10k  [RESC1005X04L]
R38  10k  [RESC1005X04L]
R39  1k  [RESC1005X04L]
R40  100R  [RESC1005X04L]
R41  1k  [RESC1005X04L]
R42  1k  [RESC1005X04L]
R43  1k  [RESC1005X04L]
R44  100R  [RESC1005X04L]
R45  1k  [RESC1005X04L]
R46  1k  [RESC1005X04L]
SB5  Solderbridge  [Solderbridge]  (value not drawn)  (no BOM)
SB6  Solderbridge  [Solderbridge]  (value not drawn)  (no BOM)
TP12  Ø1.5mm,SMD  [TP_SMD_Ø1.5mm]  (value not drawn)  (no BOM)
TP13  Ø1.5mm,SMD  [TP_SMD_Ø1.5mm]  (value not drawn)  (no BOM)
TP14  Ø1.5mm,SMD  [TP_SMD_Ø1.5mm]  (value not drawn)  (no BOM)
TP15  Ø1.5mm,SMD  [TP_SMD_Ø1.5mm]  (value not drawn)  (no BOM)
U5  MCP4451_100k  [QFN50P400X400X80_HS-21N]  (parts B,C of 5)
U7  TLV272  [MSOP65P490X110-8N]  (parts A,B of 2)
U8  AD8615  [SOT95P280X145-5N]
U9  TLV272  [MSOP65P490X110-8N]  (parts A,B of 2)
U10  MCP1824T-ADJE/OT  [SOT-23-5]
U11  LTC6752-2  [MSOP65P490X110-8N]
U12  LTC6752-2  [MSOP65P490X110-8N]
U13  LTC6752-2  [MSOP65P490X110-8N]
U14  LTC6752-2  [MSOP65P490X110-8N]
U15  74LVC1GU04  [SOT-353]
U16  74LVC2G08  [PSON35P100X50-8N]  (parts A,B of 2)
U17  74LVC1G17  [SOT-353]
U18  74LVC1G17  [SOT-353]
U19  74LVC2G08  [PSON35P100X50-8N]  (parts A,B of 2)
U20  74LVC1GU04  [SOT-353]
U21  74LVC1GU04  [SOT-353]
U22  74LVC1G17  [SOT-353]
U23  74LVC1G17  [SOT-353]
U24  74LVC2G08  [PSON35P100X50-8N]  (part A of 2)

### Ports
SE_OUT (out), SW1_ON/OFF_AUTO (out), SW2_ON/OFF_AUTO (out), VREF_OFF (out), VREF_ON (out)

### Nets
GND: C23.1 C24.1 C25.1 C26.1 C28.1 C29.1 C30.1 C31.1 C32.2 C33.1 C34.1 C35.1 C36.2 C37.1 C38.2 C39.2 C40.1 C41.2 C42.1 C43.1 C44.1 C45.2 C46.1 C47.1 C48.1 C49.1 C50.1 C51.1 C52.1 C53.1 C54.1 C55.1 C56.1 R29.1 R30.1 R32.1 R36.1 R37.1 R41.1 R45.1 U7.4(-) U8.2(VSS) U9.4(-) U10.2(GND) U11.6(VEE) U12.6(VEE) U13.6(VEE) U14.6(VEE) U15.3(GND) U16.4(GND) U17.3(GND) U18.3(GND) U19.4(GND) U20.3(GND) U21.3(GND) U22.3(GND) U23.3(GND) U24.4(GND)
V5V: C23.2 C24.2 C28.2 C30.2 C32.1 C36.1 C41.1 C45.1 U7.8(+) U8.5(VDD) U9.8(+) U10.1(VIN) U10.3(~{SHDN}) U11.1(VCC) U12.1(VCC) U13.1(VCC) U14.1(VCC)
VDD: C31.2 C33.2 C35.2 C37.2 C40.2 C42.2 C44.2 C46.2 C47.2 C48.2 C49.2 C50.2 C51.2 C52.2 C53.2 C54.2 C55.2 C56.2 R42.2 R46.2 SB5.1 SB6.1 U11.8(VDD) U12.5(~{LL}/HYST) U12.8(VDD) U13.8(VDD) U14.5(~{LL}/HYST) U14.8(VDD) U15.5(VDD) U16.8(VDD) U17.5(VDD) U18.5(VDD) U19.8(VDD) U20.5(VDD) U21.5(VDD) U22.5(VDD) U23.5(VDD) U24.8(VDD)
VDD_DUT': R25.1
VDD_DUT_PRE: U7.3(+)
VREG_REF: C29.2 R27.1 R30.2 R33.2 TP13.1 U5.11(P0B) U10.5(VOUT)
SE_OUT: C26.2 R24.2 TP12.1 U11.3(-IN) U12.3(-IN) U13.3(-IN) U14.3(-IN) ; port SE_OUT
STAGE1_OUT: R39.2 R41.2 U15.2(A) U16.3(2Y) U17.2(A)
STAGE2_OUT: R43.2 R45.2 U21.2(A) U22.2(A) U24.7(1Y)
STAGE2_OUT_INV: U16.2(1B) U19.5(2A) U21.4(Y)
STG1_OFF_SHDN: U12.4(~{SHDN}) U19.7(1Y)
STG1_ON_SHDN: U11.4(~{SHDN}) U16.7(1Y)
STG2_ON_SHDN: U13.4(~{SHDN}) U19.3(2Y)
SW1_ON/OFF_AUTO: U18.4(Y) U19.2(1B) U19.6(2B) ; port SW1_ON/OFF_AUTO
SW2_ON/OFF_AUTO: U14.4(~{SHDN}) U20.2(A) U23.4(Y) ; port SW2_ON/OFF_AUTO
VREF_OFF: C39.1 R38.2 TP15.1 U9.7(OUT) U12.2(+IN) U14.2(+IN) ; port VREF_OFF
VREF_ON: C38.1 R31.2 TP14.1 U7.7(OUT) U11.2(+IN) U13.2(+IN) ; port VREF_ON
VREF_PRE: R23.1 R28.2 R35.2 U7.1(OUT) U7.2(-)
NetC25_2: C25.2 R25.2 U8.3(IN+)
NetC27_1: C27.1 R24.1 R26.2 U8.1(OUT)
NetC27_2: C27.2 R23.2 R26.1 U8.4(IN-)
NetC34_2: C34.2 R40.2 U18.2(A)
NetC43_2: C43.2 R44.2 U23.2(A)
NetR27_2: R27.2 R31.1 U7.6(-)
NetR28_1: R28.1 R29.2 U7.5(+)
NetR32_2: R32.2 U5.10(P0W) U10.4(PG/ADJ)
NetR33_1: R33.1 U5.6(P1B)
NetR34_1: R34.1 U9.1(OUT) U9.2(-)
NetR34_2: R34.2 R38.1 U9.6(-)
NetR35_1: R35.1 R37.2 U9.5(+)
NetR36_2: R36.2 U5.7(P1W) U9.3(+)
NetR39_1: R39.1 U11.7(Q) U16.5(2A)
NetR40_1: R40.1 U17.4(Y)
NetR42_1: R42.1 U12.7(Q) U16.6(2B)
NetR43_1: R43.1 U13.7(Q) U24.1(1A)
NetR44_1: R44.1 U22.4(Y)
NetR46_1: R46.1 U14.7(Q) U24.2(1B)
NetSB5_2: SB5.2 U11.5(~{LL}/HYST)
NetSB6_2: SB6.2 U13.5(~{LL}/HYST)
NetU15_4: U15.4(Y) U16.1(1A)
NetU19_1: U19.1(1A) U20.4(Y)

Not connected (* = marked no-connect by the designer): U5 8(P1A) 9(P0A); U15 1(N.C.); U17 1(N.C.); U18 1(N.C.); U20 1(N.C.); U21 1(N.C.); U22 1(N.C.); U23 1(N.C.)

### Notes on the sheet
- Differential amplifier
- Automatic switch
- Referance voltage
- (near U5) 0-100k

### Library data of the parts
C23 C24 C30 C32 C33 C36 C37 C41 C42 C45-C56 = C0402-100n: as C4 on sheet pca63511 - Current Measurement
C25 C27 = C0402-2.2p: Capacitor, NP0, ±0.1pF; Note: 50V; Artikkelnr Noca: 20029145; Artikkelnr Simpro: N.A.
C26 = C0402-220p: Chip Cap 0402; Note: 50V; Artikkelnr Noca: 20039432; Artikkelnr Simpro: N.A.
C28 = C0402-4µ7: Chip Cap 0402; Note: 10V; Artikkelnr Noca: 20039482; Artikkelnr Simpro: N.A.
C29 = C0402-1µ0: as C18 on sheet pca63511 - Connectors and joystick
C31 C35 C40 C44 = C0402-2µ2: Chip Cap 0402; Note: 25V; Artikkelnr Noca: 20030006; Artikkelnr Simpro: N.A.
C34 C43 = C0402-1n0: Capacitor, X7R, ±10%; Note: 50V; Artikkelnr Noca: 20039223; Artikkelnr Simpro: N.A.
C38 C39 = C1206-47µ_Tantal: Capacitor, Tantalum, ±10%; Note: 10V; Artikkelnr Noca: 20049200; Artikkelnr Simpro: N.A.
R23 = R0402-1k0_0.1%: Resistor, ±0.1%, 0.063W; Note: Chip Res 0.1%; Artikkelnr Noca: 27469397; Artikkelnr Simpro: N.A.; Value Ohm: 1000
R24 = R0402-100_0.1%: Resistor, ±0.1%, 0.063W; Note: Chip Res 0.1%; Artikkelnr Noca: 27469411; Artikkelnr Simpro: N.A.; Value Ohm: 100
R25 = R0402-10R: Resistor, ±1%, 0.063W; Note: Chip Res 1%; Artikkelnr Noca: 27049025; Artikkelnr Simpro: N.A.; Value Ohm: 10
R26 = R0402-10k_0.1%: Resistor, ±0.1%, 0.063W; Note: Chip Res 0.1%; Artikkelnr Noca: 27469402; Artikkelnr Simpro: N.A.; Value Ohm: 10000
R27-R29 R31 R34 R35 R38 = R0402-10k: Resistor, ±1%, 0.063W; Note: Chip Res 1%; Artikkelnr Noca: 27049097; Artikkelnr Simpro: N.A.; Value Ohm: 10000
R30 R39 R41-R43 R45 R46 = R0402-1k0: as R50 on sheet pca63511 - Current Measurement
R32 = R0402-27k: Resistor, ±1%, 0.063W; Note: Chip Res 1%; Artikkelnr Simpro: N.A.; Value Ohm: 27000; Artikkelnr Noca: 27049107
R33 = R0402-30k: Resistor, ±1%, 0.063W; Note: Chip Res 1%; Artikkelnr Simpro: N.A.; Artikkelnr Noca: 27049108; Value Ohm: 30000
R36 = R0402-2k0: Resistor, ±1%, 0.063W; Note: Chip Res 1%; Artikkelnr Simpro: N.A.; Artikkelnr Noca: 27049080; Value Ohm: 2000
R37 = R0402-10k: Resistor, ±1%, 0.063W; Note: Chip Res 1%; Artikkelnr Simpro: N.A.; Artikkelnr Noca: 27049097; Value Ohm: 10000
R40 R44 = R0402-100: Resistor, ±1%, 0.063W; Note: Chip Res 1%; Artikkelnr Noca: 27049049; Artikkelnr Simpro: N.A.; Value Ohm: 100
SB5 SB6 = Solderbridge: Artikkelnr Noca: N.A.
TP12-TP15 = TP_SMD_Ø1.5MM: as TP6 on sheet pca63511 - Connectors and joystick
U5 = MCP4451_100k: as U5 on sheet pca63511 - Current Measurement
U7 U9 = TLV272CM8-13: Dual rail to rail CMOS Amplifier; Manufacturer: Diodes Incorporated; Artikkelnr Noca: 17010014; Artikkelnr Simpro: N.A.
U8 = AD8615AUJZ-REEL7: IC OPAMP GP 24MHZ RRO TSOT23-5; Manufacturer: Analog Devices; Artikkelnr Noca: 17010015; Artikkelnr Simpro: N.A.
U10 = MCP1824T-ADJE/OT: 300 mA, Low Voltage, Low Quiescent Current LDO Regulator; Manufacturer: Microchip; Artikkelnr Noca: 17030009; Artikkelnr Simpro: N.A.
U11-U14 = LTC6752-2: IC 2.9ns COMPARATOR, Rail-to-Rail input CMOS output, MSOP-8; Manufacturer: Linear Technology; Artikkelnr Noca: 17029058; Artikkelnr Simpro: N.A.
U15 U20 U21 = 74LVC1GU04: Unbuffered Inverter; Manufacturer: NXP Semiconductors; 2nd source part number: 163-1691; Artikkelnr Noca: 15049405; Artikkelnr Simpro: N.A.
U16 U19 U24 = 74LVC2G08GF: IC DUAL 2IN POS-AND GATE SOT-1089; Manufacturer: NXP; Note: DUAL 2-INPUT POSITIVE-AND GATE; Artikkelnr Noca: 15049067; Artikkelnr Simpro: N.A.
U17 U18 U22 U23 = 74LVC1G17SE: Single schmitt-trigger buffer with standard push-pull output; Manufacturer: Diodes; 2nd source part number: 189-3834; Artikkelnr Noca: 15049066; Artikkelnr Simpro: N.A.

## Sheet pca63511 - Power supply.SchDoc: Power Profiler - Power supply
size A4; Revision: 1.0.0; SheetNumber: 4; SheetTotal: 4; DrawnBy: RUBR; ProjectNumber: 4425; DocumentSize: A4; PCBRevision: 0232RUBR; PCAName: PCA63511; PCBNumber: 400102
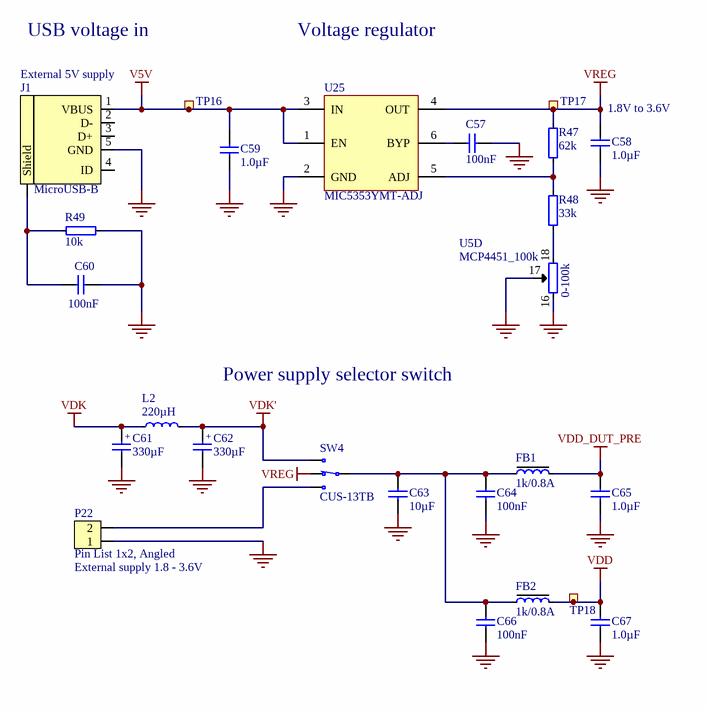
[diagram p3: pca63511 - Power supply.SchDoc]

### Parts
C57  100nF  [CAPC1005X04L]
C58  1.0µF  [CAPC1005X04L]
C59  1.0µF  [CAPC1005X04L]
C60  100nF  [CAPC1005X04L]
C61  330µF  [CAPMP3528X21N]
C62  330µF  [CAPMP3528X21N]
C63  10µF  [CAPC1608X06L]
C64  100nF  [CAPC1005X04L]
C65  1.0µF  [CAPC1005X04L]
C66  100nF  [CAPC1005X04L]
C67  1.0µF  [CAPC1005X04L]
FB1  1k/0.8A  [INDC1608X06L]
FB2  1k/0.8A  [INDC1608X06L]
J1  MicroUSB-B  [USB-Micro-B-RA-SMD-PiP]
L2  220µH  [WE-TPC_4848]
P22  Pin List 1x2, Angled  [LIST_ANG_1x2-SMD-2.54MM]
R47  62k  [RESC1005X04L]
R48  33k  [RESC1005X04L]
R49  10k  [RESC1005X04L]
SW4  CUS-13TB  [CUS-13B]
TP16  Ø1.5mm,SMD  [TP_SMD_Ø1.5mm]  (value not drawn)  (no BOM)
TP17  Ø1.5mm,SMD  [TP_SMD_Ø1.5mm]  (value not drawn)  (no BOM)
TP18  Ø1.5mm,SMD  [TP_SMD_Ø1.5mm]  (value not drawn)  (no BOM)
U5  MCP4451_100k  [QFN50P400X400X80_HS-21N]  (part D of 5)
U25  MIC5353YMT-ADJ  [QFN50P160X160X60_6N]

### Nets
GND: C57.1 C58.2 C59.2 C60.2 C61.2 C62.2 C63.1 C64.1 C65.1 C66.1 C67.1 J1.5(GND) P22.1 R49.2 U5.16(P2B) U5.17(P2W) U25.2(GND) U25.7(GND)
V5V: C59.1 J1.1(VBUS) TP16.1 U25.1(EN) U25.3(IN)
VDD: C67.2 FB2.2 TP18.1
VDD_DUT_PRE: C65.2 FB1.2
VDK: C61.1 L2.1
VDK': C62.1 L2.2 SW4.1(N.O)
VREG: C58.1 R47.2 SW4.2(N.C) TP17.1 U25.4(OUT)
NetC57_2: C57.2 U25.6(BYP)
NetC60_1: C60.1 J1.6(Shield) R49.1
NetC63_2: C63.2 C64.2 C66.2 FB1.1 FB2.1 SW4.3(COM)
NetP22_2: P22.2 SW4.4(N.O)
NetR47_1: R47.1 R48.2 U25.5(ADJ)
NetR48_1: R48.1 U5.18(P2A)

Not connected (* = marked no-connect by the designer): J1 2(D-) 3(D+) 4(ID)

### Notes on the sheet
- (near J1) External 5V supply
- USB voltage in
- Voltage regulator
- (near C58) 1.8V to 3.6V
- (near U5) 0-100k
- Power supply selector switch
- (near P22) External supply 1.8 - 3.6V

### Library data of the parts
C57 C60 C64 C66 = C0402-100n: as C4 on sheet pca63511 - Current Measurement
C58 C59 C65 C67 = C0402-1µ0: as C18 on sheet pca63511 - Connectors and joystick
C61 C62 = C3528-330µF: Capacitor, Tantalum, ±20%, 3528; Manufacturer: Kemet; Manufacturer Part Number: T490B337M006ATE800; Note: 6.3V; Artikkelnr Noca: 20049201; Artikkelnr Simpro: N.A.
C63 = C0603-10µ: Capacitor, X5R, ±20%; Note: 6.3V; Artikkelnr Noca: 20039234; Artikkelnr Simpro: N.A.
FB1 FB2 = FB0603-1k@100MHz-800mA: Ferrite Bead, 1 kOhm @ 100MHz, 800mA, 300 mOhm Max; Manufacturer: TDK; Manufacturer Part Number: MPZ1608S102ATA00; Note: Chip EMIFIL Inductor Type Chip Ferrite Bead; Artikkelnr Noca: 37029017; Artikkelnr Simpro: N.A.
J1 = USB-Micro-B-RA-SMD-PiP: MicroUSB-B-SMT; Manufacturer: Allen Creations Corp.; Manufacturer Part Number: AJU55-BS2111-L; 2nd source part number: 609-4616-1-ND; Artikkelnr Noca: 55029020; Artikkelnr Simpro: N.A.
L2 = L4848-220µH: FIXED IND 470UH 240MA 2.6 OHM; Manufacturer: Bourns; Manufacturer Part Number: SRR4028-221Y; Note: -40°C ~ 125°C; Artikkelnr Noca: 33020083; Artikkelnr Simpro: N.A.
P22 = Pin List Ang 1x2 SMD, 2.54mm: as P16 on sheet pca63511 - Connectors and joystick
R47 = R0402-62k: Resistor, ±1%, 0.063W; Note: Chip Res 1%; Artikkelnr Noca: 27049116; Artikkelnr Simpro: N.A.; Value Ohm: 62000
R48 = R0402-33k: Resistor, ±1%, 0.063W; Note: Chip Res 1%; Artikkelnr Noca: 27049109; Artikkelnr Simpro: N.A.; Value Ohm: 33000
R49 = R0402-10k: as R27 on sheet pca63511 - Automatic switch
SW4 = CUS-13TB: Low-profile slide switch, SP3T, ON-ON-ON; Manufacturer: Copal Electronics Inc; Artikkelnr Noca: 50029016; Artikkelnr Simpro: N.A.
TP16-TP18 = TP_SMD_Ø1.5MM: as TP6 on sheet pca63511 - Connectors and joystick
U5 = MCP4451_100k: as U5 on sheet pca63511 - Current Measurement
U25 = MIC5353YMT: 500mA LDO adjustable; Manufacturer: Microchip Technology; Artikkelnr Noca: 17030072; Artikkelnr Simpro: N.A.

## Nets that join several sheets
GND: pca63511 - Connectors and joystick (24 pins), pca63511 - Current Measurement (41 pins), pca63511 - Automatic switch (58 pins), pca63511 - Power supply (18 pins)
V5V: pca63511 - Connectors and joystick (5 pins), pca63511 - Current Measurement (SB8.1), pca63511 - Automatic switch (17 pins), pca63511 - Power supply (5 pins)
VDD: pca63511 - Connectors and joystick (10 pins), pca63511 - Current Measurement (22 pins), pca63511 - Automatic switch (38 pins), pca63511 - Power supply (C67.2 FB2.2 TP18.1)
VDD_DUT: pca63511 - Connectors and joystick (SW2.5), pca63511 - Current Measurement (U2.1)
VDD_DUT': pca63511 - Current Measurement (7 pins), pca63511 - Automatic switch (R25.1)
VDD_DUT_PRE: pca63511 - Current Measurement (5 pins), pca63511 - Automatic switch (U7.3), pca63511 - Power supply (C65.2 FB1.2)
VDK: pca63511 - Connectors and joystick (9 pins), pca63511 - Power supply (C61.1 L2.1)
VDK': pca63511 - Current Measurement (SB1.1), pca63511 - Power supply (C62.1 L2.2 SW4.1)
D2: pca63511 - Connectors and joystick (P10.3), pca63511 - Current Measurement (U1.37)
D3: pca63511 - Connectors and joystick (P10.4), pca63511 - Current Measurement (U1.40)
D4: pca63511 - Connectors and joystick (P10.5), pca63511 - Current Measurement (U1.2)
D9: pca63511 - Connectors and joystick (P13.2), pca63511 - Current Measurement (U1.3)
D10: pca63511 - Connectors and joystick (P13.3), pca63511 - Current Measurement (U1.8)
D11: pca63511 - Connectors and joystick (P13.4), pca63511 - Current Measurement (U1.9)
D12: pca63511 - Connectors and joystick (P13.5), pca63511 - Current Measurement (U1.10)
D13: pca63511 - Connectors and joystick (P13.6), pca63511 - Current Measurement (U1.11)
EXT_TRIG_IN: pca63511 - Connectors and joystick (P20.2), pca63511 - Current Measurement (Q4.1)
EXT_TRIG_OUT: pca63511 - Connectors and joystick (P20.1), pca63511 - Current Measurement (Q3.3 R50.1)
JOYSTICK_BUTTON_FILTERED: pca63511 - Connectors and joystick (C22.1 D6.3 R22.2), pca63511 - Current Measurement (U1.20)
JOYSTICK_DOWN_FILTERED: pca63511 - Connectors and joystick (C19.1 D3.3 R19.2), pca63511 - Current Measurement (U1.23)
JOYSTICK_LEFT_FILTERED: pca63511 - Connectors and joystick (C20.1 D4.3 R20.2), pca63511 - Current Measurement (U1.22)
JOYSTICK_RIGHT_FILTERED: pca63511 - Connectors and joystick (C21.1 D5.3 R21.2), pca63511 - Current Measurement (U1.24)
JOYSTICK_UP_FILTERED: pca63511 - Connectors and joystick (C18.1 D2.3 R18.2), pca63511 - Current Measurement (U1.27)
SCL: pca63511 - Connectors and joystick (P13.10), pca63511 - Current Measurement (R9.1 U1.39 U5.3 U6.6)
SDA: pca63511 - Connectors and joystick (P13.9), pca63511 - Current Measurement (R8.1 U1.38 U5.4 U6.5)
SE_OUT: pca63511 - Current Measurement (U1.6), pca63511 - Automatic switch (7 pins)
SW1_ON/OFF: pca63511 - Connectors and joystick (P10.1), pca63511 - Current Measurement (5 pins)
SW1_ON/OFF_AUTO: pca63511 - Current Measurement (D1.5), pca63511 - Automatic switch (U18.4 U19.2 U19.6)
SW2_ON/OFF: pca63511 - Connectors and joystick (P10.2), pca63511 - Current Measurement (5 pins)
SW2_ON/OFF_AUTO: pca63511 - Current Measurement (D1.6), pca63511 - Automatic switch (U14.4 U20.2 U23.4)
SWDCLK: pca63511 - Connectors and joystick (P19.5 P21.4 TP7.1), pca63511 - Current Measurement (U1.25)
SWDIO: pca63511 - Connectors and joystick (P19.4 P21.2 TP6.1), pca63511 - Current Measurement (U1.26)
SWO: pca63511 - Connectors and joystick (P19.6 P21.6 TP8.1), pca63511 - Current Measurement (U1.21)
SYNC1: pca63511 - Connectors and joystick (P7.1 SB3.1), pca63511 - Current Measurement (U1.18)
SYNC2: pca63511 - Connectors and joystick (P7.2 SB4.1), pca63511 - Current Measurement (U1.19)
VREF_OFF: pca63511 - Current Measurement (U1.42), pca63511 - Automatic switch (6 pins)
VREF_ON: pca63511 - Current Measurement (U1.43), pca63511 - Automatic switch (6 pins)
